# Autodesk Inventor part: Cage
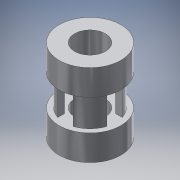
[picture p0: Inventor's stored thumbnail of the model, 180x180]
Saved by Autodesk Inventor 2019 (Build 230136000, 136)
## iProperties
Created: 2018-06
Part Number: Cage
Material: Plastique ABS
Document SubType Name: Modeling
Designer: Fabian Perrée
Density: 1.06 g/cm^3
Appearance: Lisse - Blanc
Author: Fabian Perrée
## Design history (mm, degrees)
sketch "Esquisse1"
  geometry: L1 (0, 0)-(0, 16); L2 (3, 16)-(6, 16); L3 (6, 16)-(6, 11); L4 (3, 11)-(3, 16); L5 (6, 5)-(6, 0); L6 (6, 0)-(0, 0); L7 (3, 5)-(3, 2.5); L8 (3, 2.5)-(0, 2.5); L9 (3.75, 11)-(3.75, 5); L10 (5, 11)-(5, 5); L11 (6, 11)-(5, 11); L12 (3.75, 11)-(3, 11); L13 (6, 5)-(5, 5); L14 (3.75, 5)-(3, 5)
  constraints: 28 end point, 8 perpendicular, 4 collinear, 4 horizontal, 4 point on line, 3 parallel, 1 vertical
  dimensions: "d0" = 16 distance of L1.start L1.end; "d2" = 12 diameter of L3 L1; "d3" = 6 diameter of L4 L1; "d4" = 5 distance of L2.end L3.end; "d7" = 13.5 distance between parallel lines of L2 L8; "d8" = 7.5 diameter of L9 L1; "d9" = 10 diameter of L10 L1; "d10" = 6 distance between parallel lines of L11 L13
revolve "Révolution1" sketch "Esquisse1" stored, may be unused: angle "d11" = 90 deg
sketch "Esquisse2"
  geometry: L1 (-5.809, -1.5)-(-2.598, -1.5); L2 (-2.598, -1.5)-(-2.598, 1.5); L3 (-2.598, 1.5)-(-5.809, 1.5); L4 (-5.809, 1.5)-(-5.809, -1.5); L5 (-6, 0)-(0, 0); A1 r 6 centre (0, 0) between (-5.809, -1.5) and (-6, 0) reference; 1 further point
  constraints: 10 end point, 2 parallel, 2 perpendicular, 2 point on circle, 1 horizontal, 3 other
  dimensions: "d12" = 3 distance of L3.end L1.start
extrude "Extrusion1" cut sketch "Esquisse2" stored distance "d13" = 10; taper "d14" = 0 deg
pattern_circular "Réseau circulaire1" dims angle "d16" = 360 deg
feature "Scission1"
node "Solide1"
other parameters: "d6" = 6
